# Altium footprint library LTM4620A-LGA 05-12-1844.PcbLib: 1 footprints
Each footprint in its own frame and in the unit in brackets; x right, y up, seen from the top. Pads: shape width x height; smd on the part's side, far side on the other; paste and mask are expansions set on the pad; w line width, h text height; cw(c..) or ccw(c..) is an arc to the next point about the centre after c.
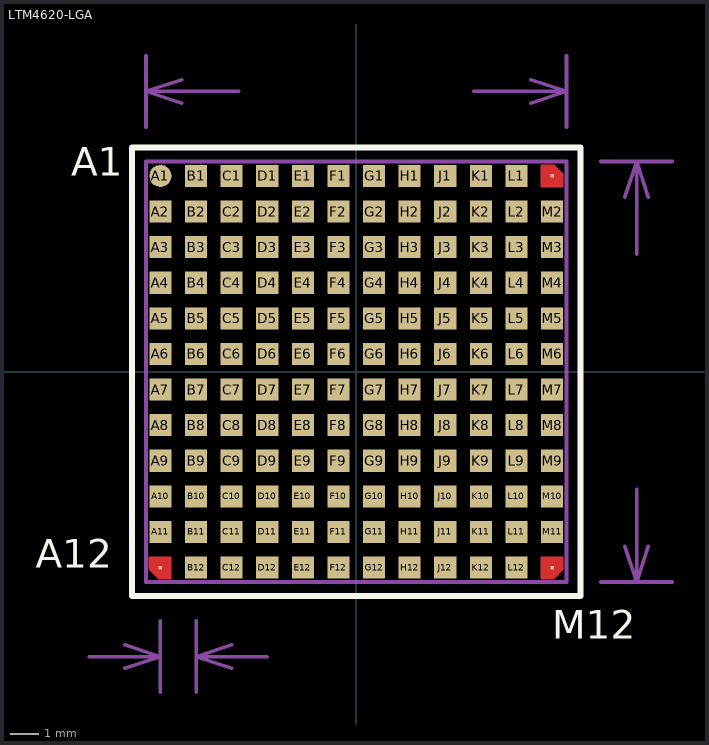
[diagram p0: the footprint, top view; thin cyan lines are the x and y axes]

## LTM4620-LGA [mil]
pads (144):
  round 31 smd paste-3.5 mask-3: A1(-275,275)
  rect 31x31 smd paste-3.5 mask-3: A2(-275,225) A3(-275,175) A4(-275,125) A5(-275,75) A6(-275,25) A7(-275,-25) A8(-275,-75) A9(-275,-125) A10(-275,-175) A11(-275,-225) B1(-225,275) B2(-225,225) B3(-225,175) B4(-225,125) B5(-225,75) B6(-225,25) B7(-225,-25) B8(-225,-75) B9(-225,-125) B10(-225,-175) B11(-225,-225) B12(-225,-275) C1(-175,275) C2(-175,225) C3(-175,175) C4(-175,125) C5(-175,75) C6(-175,25) C7(-175,-25) C8(-175,-75) C9(-175,-125) C10(-175,-175) C11(-175,-225) C12(-175,-275) D1(-125,275) D2(-125,225) D3(-125,175) D4(-125,125) D5(-125,75) D6(-125,25) D7(-125,-25) D8(-125,-75) D9(-125,-125) D10(-125,-175) D11(-125,-225) D12(-125,-275) E1(-75,275) E2(-75,225) E3(-75,175) E4(-75,125) E5(-75,75) E6(-75,25) E7(-75,-25) E8(-75,-75) E9(-75,-125) E10(-75,-175) E11(-75,-225) E12(-75,-275) F1(-25,275) F2(-25,225) F3(-25,175) F4(-25,125) F5(-25,75) F6(-25,25) F7(-25,-25) F8(-25,-75) F9(-25,-125) F10(-25,-175) F11(-25,-225) F12(-25,-275) G1(25,275) G2(25,225) G3(25,175) G4(25,125) G5(25,75) G6(25,25) G7(25,-25) G8(25,-75) G9(25,-125) G10(25,-175) G11(25,-225) G12(25,-275) H1(75,275) H2(75,225) H3(75,175) H4(75,125) H5(75,75) H6(75,25) H7(75,-25) H8(75,-75) H9(75,-125) H10(75,-175) H11(75,-225) H12(75,-275) J1(125,275) J2(125,225) J3(125,175) J4(125,125) J5(125,75) J6(125,25) J7(125,-25) J8(125,-75) J9(125,-125) J10(125,-175) J11(125,-225) J12(125,-275) K1(175,275) K2(175,225) K3(175,175) K4(175,125) K5(175,75) K6(175,25) K7(175,-25) K8(175,-75) K9(175,-125) K10(175,-175) K11(175,-225) K12(175,-275) L1(225,275) L2(225,225) L3(225,175) L4(225,125) L5(225,75) L6(225,25) L7(225,-25) L8(225,-75) L9(225,-125) L10(225,-175) L11(225,-225) L12(225,-275) M2(275,225) M3(275,175) M4(275,125) M5(275,75) M6(275,25) M7(275,-25) M8(275,-75) M9(275,-125) M10(275,-175) M11(275,-225)
  rect 5x5 smd paste-3.5 mask-3: A12(-275,-275) M1(275,275) M12(275,-275)
TopLayer:
  region: 259.5,290.5 259.5,259.5 290.5,259.5 290.5,277.5 277.5,290.5
  region: 259.5,-259.5 259.5,-290.5 277.5,-290.5 290.5,-277.5 290.5,-259.5
  region: -290.5,-259.5 -259.5,-259.5 -259.5,-290.5 -277.5,-290.5 -290.5,-277.5
  lines w0.39: -290.5,-277.5 -290.5,-259.5 -259.5,-259.5 -259.5,-290.5 -277.5,-290.5 -290.5,-277.5 ; 259.5,-290.5 259.5,-259.5 290.5,-259.5 290.5,-277.5 277.5,-290.5 259.5,-290.5 ; 259.5,259.5 259.5,290.5 277.5,290.5 290.5,277.5 290.5,259.5 259.5,259.5
TopOverlay:
  lines w8: -314.96,-314.96 -314.96,314.96 314.96,314.96 314.96,-314.96 -314.96,-314.96
  text "A1" at -400,275 h40
  text "A12" at -450,-275 h40
  text "M12" at 275,-375 h40
Mechanical16:
  lines w5: -375,-400 -275,-400 ; -325,-416.67 -275,-400 ; -325,-383.33 -275,-400 ; -295.28,343.7 -295.28,443.7 ; -275,-450 -275,-350 ; -245.28,377.03 -295.28,393.7 ; -245.28,410.37 -295.28,393.7 ; -225,-450 -225,-350 ; -175,-416.67 -225,-400 ; -175,-383.33 -225,-400 ; -164.95,393.7 -295.28,393.7 ; -125,-400 -225,-400 ; 164.95,393.7 295.28,393.7 ; 245.28,377.03 295.28,393.7 ; 245.28,410.37 295.28,393.7 ; 295.28,343.7 295.28,443.7 ; 343.7,-295.28 443.7,-295.28 ; 343.7,295.28 443.7,295.28 ; 377.03,-245.28 393.7,-295.28 ; 377.03,245.28 393.7,295.28 ; 393.7,-164.95 393.7,-295.28 ; 393.7,164.95 393.7,295.28 ; 410.37,-245.28 393.7,-295.28 ; 410.37,245.28 393.7,295.28 ; -295.28,-295.28 295.28,-295.28 295.28,295.28 -295.28,295.28 -295.28,-295.28
  text "1.27 (mm)" at -450.77,-519.97 h50
  text "15 (mm)" at 423.69,-154.95 h50
  text "15 (mm)" at -154.95,363.71 h50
